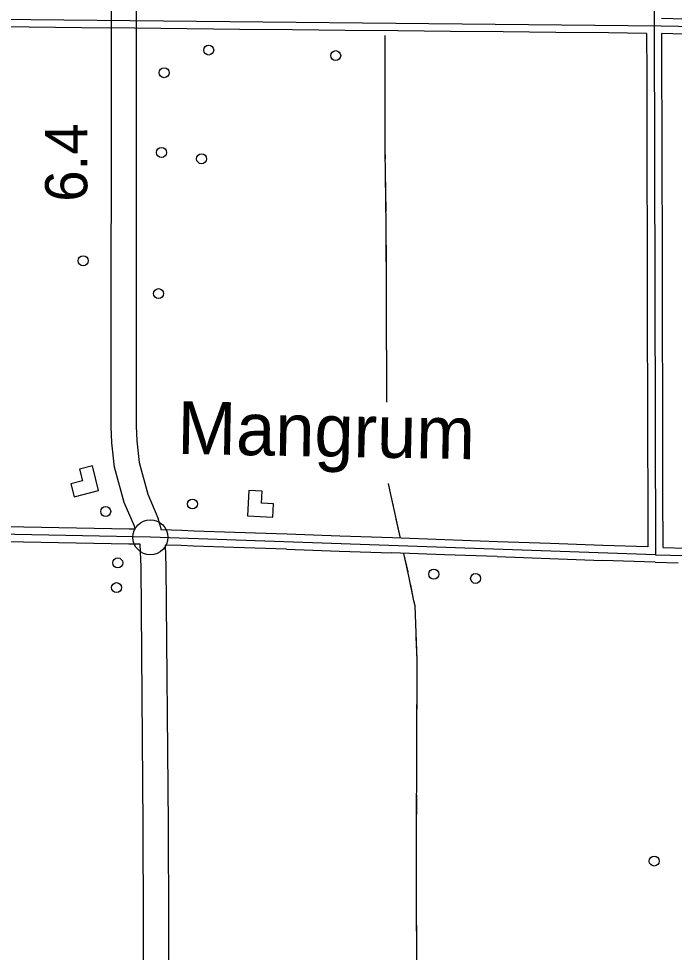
# Model space of a CAD drawing. Extents: x -4306 to 3843, y 131 to 8053.
# Drawn here: x -1303 to -251, y 4712 to 6210 of the extents above; entities that cross this region are included whole.
import ezdxf

# ---------------------------------------------------------------- set-up
doc = ezdxf.new("R2010")
doc.units = 0
for name, color, linetype in [('10', 7, 'Continuous'), ('24', 7, 'Continuous'), ('31', 7, 'Continuous'), ('32', 7, 'Continuous'), ('43', 7, 'Continuous'), ('48', 7, 'Continuous'), ('56', 7, 'Continuous'), ('58', 7, 'Continuous')]:
    doc.layers.add(name, color=color, linetype=linetype)

msp = doc.modelspace()

# ---------------------------------------------------------------- linework, layer by layer
at = {"layer": '10'}
for points in [[(-1115.9, 5392.1), (-1117, 5396), (-1133.5, 5434.2), (-1148.9, 5491), (-1153.2, 5529.9), (-1154.3, 5556.1), (-1153.9, 6206.8), (-1154.7, 6376.4)], [(-1114.6, 6374.8), (-1113.9, 6206.9), (-1114.3, 5556.9), (-1113.3, 5533), (-1109.5, 5498.5), (-1095.6, 5447.4), (-1079.2, 5409.3), (-1073.9, 5390.1)], [(-1102.4, 4507.2), (-1102, 4600.1), (-1102.8, 4916.5), (-1106.4, 5331), (-1107.8, 5367)], [(-1067.7, 5365.9), (-1066.4, 5331.9), (-1062.8, 4916.7), (-1062, 4600.1), (-1062.4, 4507.1)]]:
    msp.add_lwpolyline(points, dxfattribs=at)
at = {"layer": '24'}
msp.add_circle((-1091.3, 5378.3), 28, dxfattribs=at)
at = {"layer": '31'}
for p, q in [((-1041, 5389), (-1073.9, 5390.1)), ((-1021.2, 5388.3), (-1041, 5389)), ((-956.5, 5386), (-1021.2, 5388.3)), ((-872.1, 5383.1), (-956.5, 5386)), ((-1041.8, 5365), (-1067.7, 5365.9)), ((-1022, 5364.3), (-1041.8, 5365)), ((-957.4, 5362), (-1022, 5364.3)), ((-618.8, 5374.2), (-703.2, 5377.2)), ((-534.3, 5371.2), (-618.8, 5374.2)), ((-293.5, 5362.8), (-365.5, 5365.3)), ((-872.9, 5359.1), (-957.4, 5362)), ((-704, 5353.2), (-704, 5353.2)), ((-619.6, 5350.2), (-704, 5353.2)), ((-535.2, 5347.3), (-619.6, 5350.2)), ((-269.5, 5362), (-232.4, 5361)), ((-366.3, 5341.3), (-366.3, 5341.3)), ((-281.9, 5338.4), (-366.3, 5341.3)), ((-281.8, 5338.4), (-244.9, 5337.3))]:
    msp.add_line(p, q, dxfattribs=at)
for points in [[(-787.6, 5380.1), (-872.1, 5383.1)], [(-703.2, 5377.2), (-787.6, 5380.1)], [(-449.9, 5368.3), (-534.3, 5371.2)], [(-365.5, 5365.3), (-449.9, 5368.3)], [(-872.9, 5359.1), (-788.5, 5356.1)], [(-788.5, 5356.1), (-704, 5353.2)], [(-535.2, 5347.3), (-450.7, 5344.3)], [(-450.7, 5344.3), (-366.3, 5341.3)]]:
    msp.add_lwpolyline(points, dxfattribs=at)
at = {"layer": '32'}
for p, q in [((-277.8, 7052), (-283.5, 6198.8)), ((-271.9, 6198.6), (-1756.9, 6213.2)), ((-252.7, 6210.1), (-271.6, 6210.6)), ((-168.2, 6208), (-252.7, 6210.1)), ((-1285.8, 6196.5), (-1370.3, 6197.4)), ((-1201.3, 6195.7), (-1285.8, 6196.5)), ((-1116.8, 6194.9), (-1201.3, 6195.7)), ((-1032.4, 6194), (-1116.8, 6194.9)), ((-947.9, 6193.2), (-1032.4, 6194)), ((-863.4, 6192.4), (-947.9, 6193.2)), ((-778.9, 6191.5), (-863.4, 6192.4)), ((-694.4, 6190.7), (-778.9, 6191.5)), ((-609.9, 6189.9), (-694.4, 6190.7)), ((-525.5, 6189.1), (-609.9, 6189.9)), ((-441, 6188.2), (-525.5, 6189.1)), ((-356.5, 6187.4), (-441, 6188.2)), ((-295.5, 6186.8), (-356.5, 6187.4)), ((-295.5, 6186.8), (-295.3, 6122.6)), ((-283.5, 6198.8), (-281.4, 5350.4)), ((569.1, 6177.8), (-271.9, 6198.6)), ((-271.5, 6186.5), (-271.3, 6122.7)), ((-253.3, 6186.1), (-271.5, 6186.5)), ((-168.8, 6184), (-253.3, 6186.1)), ((-295.3, 6122.6), (-295.1, 6038.1)), ((-271.3, 6122.7), (-271.1, 6038.2)), ((-295.1, 6038.1), (-294.9, 5953.7)), ((-271.1, 6038.2), (-270.9, 5953.7)), ((-294.9, 5953.7), (-294.7, 5869.2)), ((-270.9, 5953.7), (-270.7, 5869.2)), ((-294.7, 5869.2), (-294.5, 5784.7)), ((-270.7, 5869.2), (-270.5, 5784.7)), ((-294.5, 5784.7), (-294.3, 5700.2)), ((-270.5, 5784.7), (-270.3, 5700.2)), ((-294.3, 5700.2), (-294.1, 5615.7)), ((-270.3, 5700.2), (-270.1, 5615.8)), ((-294.1, 5615.7), (-293.9, 5531.2)), ((-270.1, 5615.8), (-269.9, 5531.3)), ((-293.9, 5531.2), (-293.7, 5446.7)), ((-269.9, 5531.3), (-269.7, 5446.8)), ((-293.7, 5446.7), (-293.5, 5362.8)), ((-269.7, 5446.8), (-269.5, 5362.3)), ((-1091.2, 5378.7), (-1896.6, 5393.4)), ((-1294.6, 5394.4), (-1379, 5396)), ((-1210.1, 5392.9), (-1294.6, 5394.4)), ((-1125.6, 5391.4), (-1210.1, 5392.9)), ((-1116.2, 5391.2), (-1125.6, 5391.4)), ((-281.4, 5350.4), (-1091.2, 5378.7)), ((-1295, 5370.4), (-1379.5, 5372)), ((-1210.5, 5368.9), (-1295, 5370.4)), ((-1126, 5367.4), (-1210.5, 5368.9)), ((-1107.8, 5367), (-1126, 5367.4)), ((-281.4, 5350.4), (-232.8, 5349))]:
    msp.add_line(p, q, dxfattribs=at)
at = {"layer": '43'}
for points in [[(-712, 5594.9), (-712.7, 5761.9), (-712.9, 5877.8), (-714.5, 5999.7), (-715, 6183.2)], [(-714.9, 6154.6), (-715, 6183.2)], [(-714.8, 6101.8), (-714.9, 6133.5)], [(-714.7, 6070.1), (-714.8, 6101.8)], [(-714.3, 5985.6), (-714.5, 5999.7), (-714.6, 6049)], [(-713.2, 5901.2), (-714, 5964.5)], [(-712.8, 5816.7), (-712.9, 5877.8), (-712.9, 5880)], [(-712.6, 5732.2), (-712.7, 5761.9), (-712.8, 5795.6)], [(-712.2, 5647.7), (-712.5, 5711.1)], [(-712, 5594.9), (-712.2, 5626.6)], [(-690, 5376.7), (-705.5, 5446.7), (-709.4, 5464.8)], [(-701.4, 5428.3), (-705.5, 5446.7), (-709.4, 5464.8)], [(-690, 5376.7), (-696.9, 5407.6)], [(-664, 4510.8), (-663.1, 4574.9), (-664.4, 4780.1), (-664.5, 4897), (-663.2, 5181.9), (-666.9, 5268.2), (-668.6, 5276.5), (-676.6, 5316), (-684.7, 5352.5)], [(-678.1, 5322.8), (-684.7, 5352.5)], [(-665.7, 5239.5), (-666.9, 5268.2), (-668.6, 5276.5), (-673.8, 5302.2)], [(-663.4, 5155.1), (-663.2, 5181.9), (-664.8, 5218.4)], [(-663.7, 5070.6), (-663.5, 5133.9)], [(-664, 5017.8), (-663.8, 5049.4)], [(-664.1, 4986.1), (-664, 5017.8)], [(-664.5, 4901.6), (-664.2, 4965)], [(-664.4, 4817.1), (-664.5, 4880.5)], [(-664.1, 4732.6), (-664.4, 4780.1), (-664.4, 4796)]]:
    msp.add_lwpolyline(points, dxfattribs=at)
at = {"layer": '56'}
for centre in [(-997.8, 6160), (-794.1, 6151.1), (-1069.2, 6123.7), (-1073.5, 5995.8), (-1009.3, 5985.6), (-1199.2, 5821.9), (-1078.2, 5769.2), (-1023.9, 5431.7), (-1163, 5419.7), (-1143.7, 5337.2), (-636.8, 5319.1), (-569.7, 5312.3), (-1145.6, 5297.5), (-283.2, 4858.8)]:
    msp.add_circle(centre, 8, dxfattribs=at)
at = {"layer": '58'}
for points in [[(-1174.4, 5453.4), (-1184.3, 5492.8), (-1205.1, 5487.5), (-1200.4, 5468.9), (-1219, 5464.2), (-1213.8, 5443.4)], [(-935.6, 5412.5), (-895, 5410.5), (-894, 5432), (-913.2, 5432.9), (-912.2, 5452.1), (-933.6, 5453.1)]]:
    msp.add_lwpolyline(points, close=True, dxfattribs=at)

# ---------------------------------------------------------------- texts
at = {"layer": '24'}
msp.add_text('Mangrum', height=84.49, rotation=358.9554, dxfattribs=at).set_placement((-1048.6, 5512.1))
at = {"layer": '48'}
msp.add_text('6.4', height=67.59, rotation=90.1036, dxfattribs=at).set_placement((-1192.5, 5916.7))

doc.saveas('drawing.dxf')
